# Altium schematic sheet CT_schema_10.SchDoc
size 146 x 119 mm
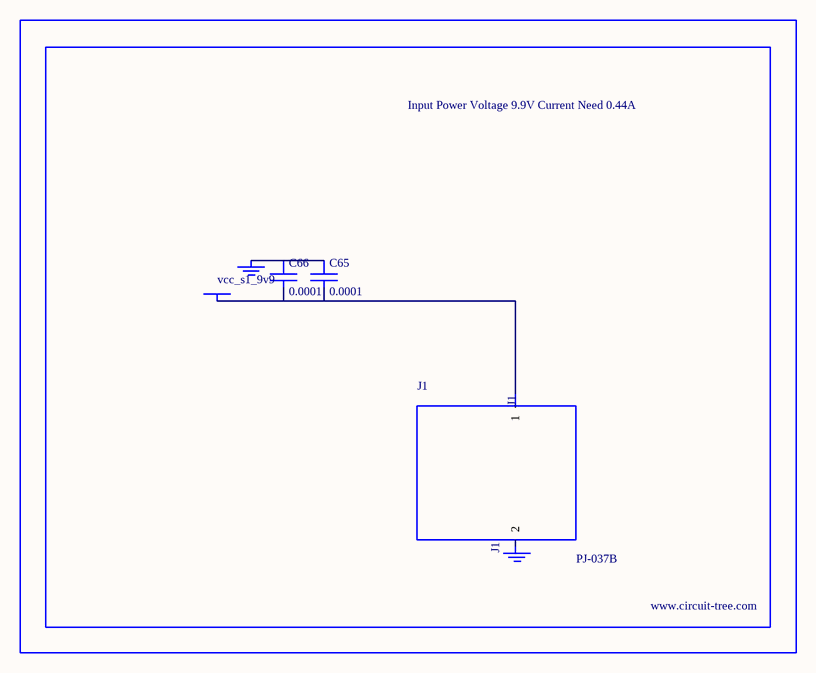
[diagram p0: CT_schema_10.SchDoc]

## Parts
BORDER9  (no value)
C65  0.0001  [EXV-9H]
C66  0.0001  [EXV-9H]
GND_INSTANCE_9_0  (no value)
GND_INSTANCE_9_1  (no value)
J1  PJ-037B  [PJ-037B_PACKAGE]
POWER_INSTANCE_9_0  vcc_s1_9v9

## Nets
NetC65_1: C65.1 C66.1 GND_INSTANCE_9_0.0(GND)
NetC65_2: C65.2 C66.2 J1.1 POWER_INSTANCE_9_0.0(PWR)

Not connected (* = marked no-connect by the designer): GND_INSTANCE_9_1 0(GND); J1 2

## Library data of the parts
BORDER9 = BORDER_PAGE9
C65 C66 = EDK107M035A9HAA
GND_INSTANCE_9_0 GND_INSTANCE_9_1 = GND
POWER_INSTANCE_9_0 = PWR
